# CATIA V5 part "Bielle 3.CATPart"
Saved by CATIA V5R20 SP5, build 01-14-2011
Part number: Bielle 3
Bounding box of the stored display mesh (mm): x -210 to 10, y -260 to -240, z 15 to 25
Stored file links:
  U:\CFAO\Thinkmotion\Bielle 3.CATPart
  U:\CFAO\Thinkmotion\Bras Articule.CATProduct
  U:\CFAO\Thinkmotion\Squelette Bielle 4.CATPart
  U:\CFAO\Thinkmotion\Squelette Bielle 3.CATPart
  U:\CFAO\Thinkmotion\Bielle 2.CATPart
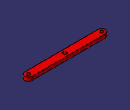
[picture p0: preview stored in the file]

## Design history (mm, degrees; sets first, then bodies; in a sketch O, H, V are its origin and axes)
Set1
  Plane1: linked copy from another document
  Line1: linked copy from another document
  Point1: linked copy from another document
  Point2: linked copy from another document
  DatumCurve1: linked copy from another document
Body1 (main body)
  Sketch1 on Plane1, origin (0, 0, 20), H (1, 0, 0), V (0, 1, 0)
    line L1 (-200, -240) -> (0, -240)
    point P2 (0, -240)
    arc A1 centre (0, -250) radius 10 from (0, -240) to (0, -260) cw
    line L2 (0, -260) -> (-200, -260)
    arc A2 centre (-200, -250) radius 10 from (-200, -260) to (-200, -240) cw
    reference projected line E1 (0, -250) -> (-100, -250) from Line1
    reference projected point E2 (-200, -250) from Point1
    reference projected point E3 (0, -250) from Point2
    circle A3 centre (-200, -250) radius 5
    circle A4 centre (0, -250) radius 5
    point P7 (0, -255)
    circle A5 centre (-100, -250) radius 5
    reference projected arc E4 centre (-100, -250) radius 10 from (-110, -250) to (-100, -260) ccw from edge of DatumCurve1
    radius A2 = 10
    radius A5 = 5
    radius A3 = 5
    radius A4 = 5
    coincidence: P2 V, A4 P7, P7 V
    horizontal: L1 H
    tangency: A1 L1, L2 A1, A2 L1, A2 L2
    symmetry: L1 L2 E1
    concentricity: A2 E2, A1 E3, A1 A4, A3 A2, A5 E4
  Pad1: profile Sketch1, direction (0, 0, 1), length 5, mirrored extent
